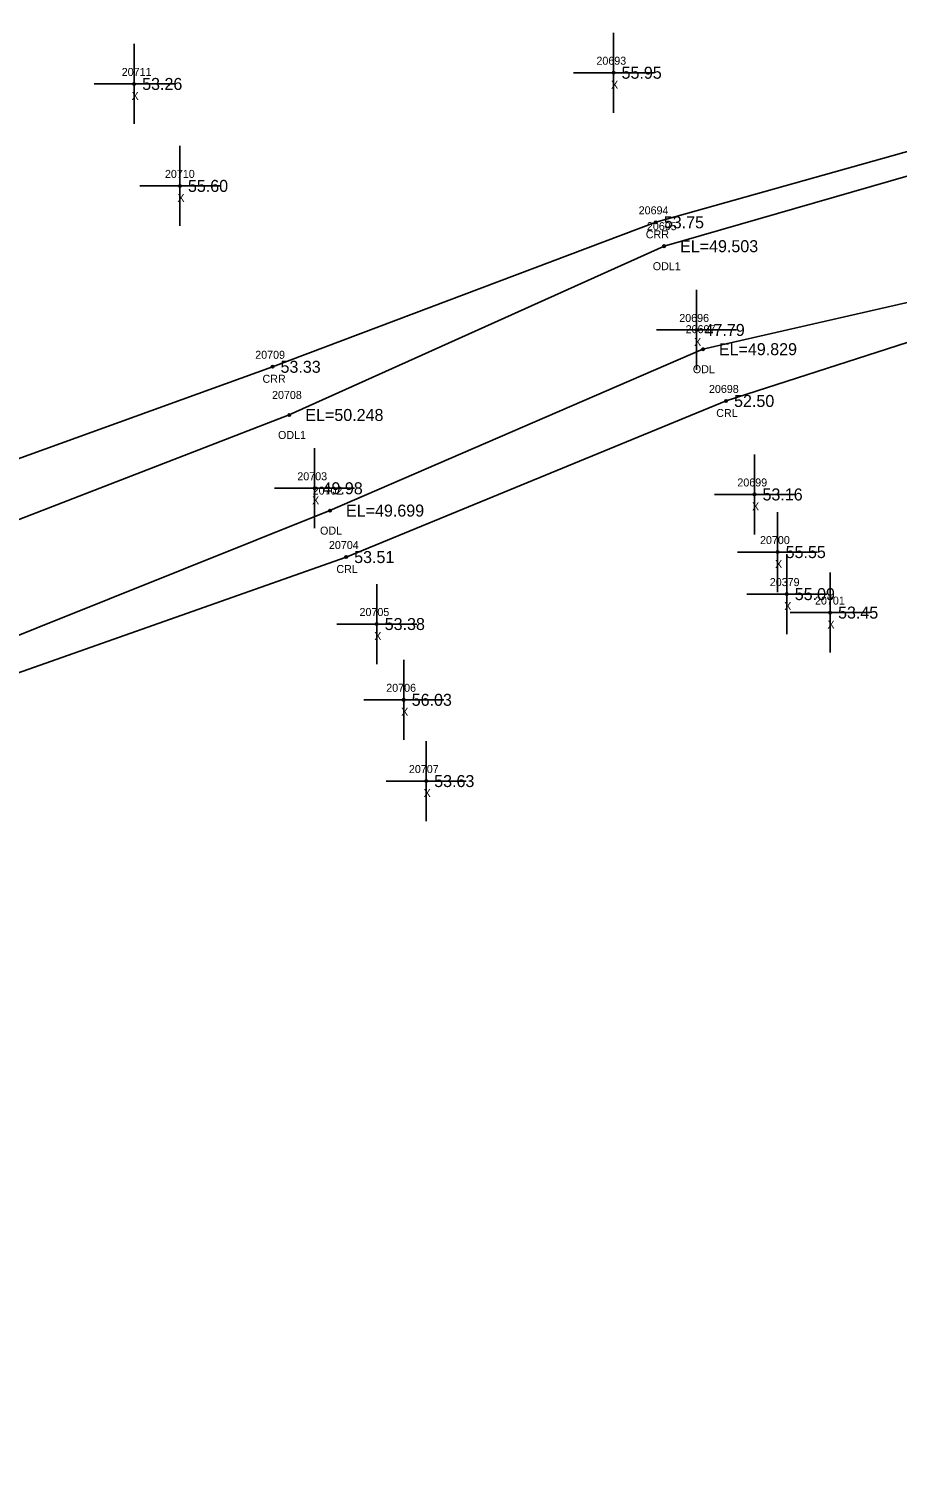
# Model space of a CAD drawing. Extents: x 2396547 to 2397655, y 770185 to 772649.
# Drawn here: x 2396902.9 to 2397011.4, y 771213.4 to 771393.4 of the extents above; entities that cross this region are included whole.
import ezdxf

# ---------------------------------------------------------------- set-up
doc = ezdxf.new("R2010")
doc.units = 0
for name, color, linetype in [('RD_EX_H2O', 7, 'Continuous'), ('RD_EX_H2O_txCode', 7, 'Continuous'), ('RD_EX_Misc', 7, 'Continuous'), ('RD_EX_Misc_txCode', 7, 'Continuous'), ('RD_EX_TX_H2O_ELEV', 7, 'Continuous'), ('RD_EX_TX_Misc_ELEV', 7, 'Continuous'), ('RD_SMD_Locator', 7, 'Continuous')]:
    doc.layers.add(name, color=color, linetype=linetype)

msp = doc.modelspace()

# ---------------------------------------------------------------- linework, layer by layer
at = {"layer": 'RD_EX_H2O'}
for points in [[(2397026.41, 771393.39), (2397025.73, 771381.74), (2396981.24, 771369.21), (2396933.35, 771351.16), (2396867.1, 771327.21), (2396805.16, 771301.5), (2396726.77, 771268.25), (2396662.72, 771245.88), (2396570.19, 771208.11)], [(2397042.3, 771381.6), (2397026.95, 771379.1), (2396982.27, 771366.23), (2396935.45, 771345.14), (2396869.6, 771319.67), (2396806.56, 771295.91), (2396727.11, 771265.36), (2396664.85, 771241.65), (2396575.64, 771198.56)], [(2397029.25, 771363), (2396987.12, 771353.36), (2396940.53, 771333.19), (2396876.37, 771307.51), (2396813.23, 771283.31), (2396732.14, 771250.38), (2396668.87, 771226.62), (2396581.1, 771189.01)], [(2397041.52, 771355.95), (2397038.66, 771356.79), (2397028.89, 771358.5), (2397025.33, 771358.42), (2397018.97, 771356.22), (2396990.02, 771346.89), (2396942.55, 771327.39), (2396877.94, 771304.58), (2396814.23, 771281.47), (2396733.01, 771246.09), (2396670.48, 771223.24), (2396582.44, 771186.21)]]:
    msp.add_lwpolyline(points, dxfattribs=at)
at = {"layer": 'RD_EX_Misc'}
for p, q in [((2396916.06, 771381.5), (2396916.06, 771391.5)), ((2396975.96, 771382.9), (2396975.96, 771392.9)), ((2396970.96, 771387.9), (2396980.96, 771387.9)), ((2396911.06, 771386.5), (2396921.06, 771386.5)), ((2396921.78, 771368.76), (2396921.78, 771378.76)), ((2396916.78, 771373.76), (2396926.78, 771373.76)), ((2396986.33, 771350.76), (2396986.33, 771360.76)), ((2396981.33, 771355.76), (2396991.33, 771355.76)), ((2396938.6, 771330.98), (2396938.6, 771340.98)), ((2396993.57, 771330.21), (2396993.57, 771340.21)), ((2396933.6, 771335.98), (2396943.6, 771335.98)), ((2396988.57, 771335.21), (2396998.57, 771335.21)), ((2396996.46, 771323.01), (2396996.46, 771333.01)), ((2396991.46, 771328.01), (2397001.46, 771328.01)), ((2396997.6, 771317.76), (2396997.6, 771327.76)), ((2397003.01, 771315.45), (2397003.01, 771325.45)), ((2396946.37, 771314.02), (2396946.37, 771324.02)), ((2396992.6, 771322.76), (2397002.6, 771322.76)), ((2396998.01, 771320.45), (2397008.01, 771320.45)), ((2396941.37, 771319.02), (2396951.37, 771319.02)), ((2396949.74, 771304.55), (2396949.74, 771314.55)), ((2396944.74, 771309.55), (2396954.74, 771309.55)), ((2396952.55, 771294.4), (2396952.55, 771304.4)), ((2396947.55, 771299.4), (2396957.55, 771299.4))]:
    msp.add_line(p, q, dxfattribs=at)
at = {"layer": 'RD_SMD_Locator'}
for centre in [(2396975.96, 771387.9), (2396916.06, 771386.5), (2396921.78, 771373.76), (2396981.24, 771369.21), (2396982.27, 771366.23), (2396986.33, 771355.76), (2396987.12, 771353.36), (2396933.35, 771351.16), (2396990.02, 771346.89), (2396935.45, 771345.14), (2396938.6, 771335.98), (2396993.57, 771335.21), (2396940.53, 771333.19), (2396942.55, 771327.39), (2396996.46, 771328.01), (2396997.6, 771322.76), (2397003.01, 771320.45), (2396946.37, 771319.02), (2396949.74, 771309.55), (2396952.55, 771299.4)]:
    msp.add_circle(centre, 0.15, dxfattribs=at)

# ---------------------------------------------------------------- texts
at = {"layer": 'RD_EX_H2O_txCode'}
for s, p in [('20694', (2396979.1, 771370.21)), ('CRR', (2396979.99, 771367.21)), ('20695', (2396980.13, 771368.23)), ('ODL1', (2396980.86, 771363.23)), ('20697', (2396984.97, 771355.36)), ('20709', (2396931.19, 771352.16)), ('CRR', (2396932.1, 771349.16)), ('ODL', (2396985.87, 771350.36)), ('20698', (2396987.88, 771347.89)), ('20708', (2396933.29, 771347.14)), ('CRL', (2396988.79, 771344.89)), ('ODL1', (2396934.04, 771342.14)), ('20702', (2396938.37, 771335.19)), ('ODL', (2396939.29, 771330.19)), ('20704', (2396940.4, 771328.39)), ('CRL', (2396941.33, 771325.39))]:
    msp.add_text(s, height=1, dxfattribs=at).set_placement(p)
at = {"layer": 'RD_EX_Misc_txCode'}
for s, p in [('20693', (2396973.82, 771388.9)), ('20711', (2396914.51, 771387.5)), ('X', (2396975.65, 771385.9)), ('X', (2396915.74, 771384.5)), ('20710', (2396919.91, 771374.76)), ('X', (2396921.47, 771371.76)), ('20696', (2396984.17, 771356.76)), ('X', (2396986.02, 771353.76)), ('20703', (2396936.45, 771336.98)), ('20699', (2396991.43, 771336.21)), ('X', (2396938.29, 771333.98)), ('X', (2396993.26, 771333.21)), ('20700', (2396994.26, 771329.01)), ('X', (2396996.14, 771326.01)), ('20379', (2396995.48, 771323.76)), ('X', (2396997.28, 771320.76)), ('20701', (2397001.13, 771321.45)), ('20705', (2396944.22, 771320.02)), ('X', (2396946.06, 771317.02)), ('X', (2397002.69, 771318.45)), ('20706', (2396947.56, 771310.55)), ('X', (2396949.42, 771307.55)), ('20707', (2396950.39, 771300.4)), ('X', (2396952.23, 771297.4))]:
    msp.add_text(s, height=1, dxfattribs=at).set_placement(p)
at = {"layer": 'RD_EX_TX_H2O_ELEV'}
for s, p in [('53.75', (2396982.24, 771368.46)), ('EL=49.503', (2396984.27, 771365.48)), ('EL=49.829', (2396989.12, 771352.61)), ('53.33', (2396934.35, 771350.41)), ('52.50', (2396991.02, 771346.14)), ('EL=50.248', (2396937.45, 771344.39)), ('EL=49.699', (2396942.53, 771332.44)), ('53.51', (2396943.55, 771326.64))]:
    msp.add_text(s, height=1.5, dxfattribs=at).set_placement(p)
at = {"layer": 'RD_EX_TX_Misc_ELEV'}
for s, p in [('55.95', (2396976.96, 771387.15)), ('53.26', (2396917.06, 771385.75)), ('55.60', (2396922.78, 771373.01)), ('47.79', (2396987.33, 771355.01)), ('49.98', (2396939.6, 771335.23)), ('53.16', (2396994.57, 771334.46)), ('55.55', (2396997.46, 771327.26)), ('55.09', (2396998.6, 771322.01)), ('53.38', (2396947.37, 771318.27)), ('53.45', (2397004.01, 771319.7)), ('56.03', (2396950.74, 771308.8)), ('53.63', (2396953.55, 771298.65))]:
    msp.add_text(s, height=1.5, dxfattribs=at).set_placement(p)

doc.saveas('drawing.dxf')
